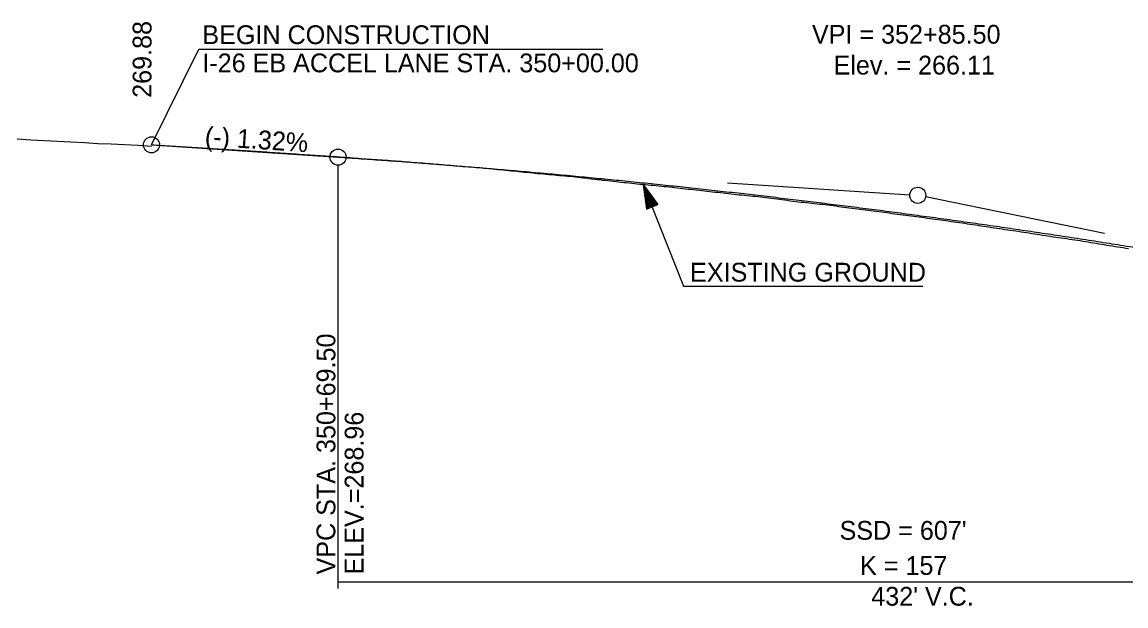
# Model space of a CAD drawing. Extents: x 69 to 2003113, y 512 to 837401.
# Drawn here: x 1913314.9 to 1913726.1, y 828640.4 to 828857.9 of the extents above; entities that cross this region are included whole.
import ezdxf

# ---------------------------------------------------------------- set-up
doc = ezdxf.new("R2010")
doc.units = 0
for name, color, linetype in [('BR_CENTER LINE BASELINE', 7, 'Continuous'), ('BR_CONCRETE', 7, 'Continuous'), ('BR_GRID DOTS', 7, 'Continuous'), ('BR_GRID LINES', 7, 'Continuous'), ('BR_TEXT', 7, 'Continuous'), ('RD_PD_ALT1_TrvlWay', 7, 'Continuous'), ('RD_SHT_IplotShp', 7, 'Continuous')]:
    doc.layers.add(name, color=color, linetype=linetype)

msp = doc.modelspace()

# ---------------------------------------------------------------- linework, layer by layer
at = {"layer": 'BR_CENTER LINE BASELINE'}
for p, q in [((1913577.73, 828798.04), (1913645.59, 828793.57)), ((1913718.15, 828779.19), (1913651.52, 828792.77))]:
    msp.add_line(p, q, dxfattribs=at)
for centre in [(1913363.08, 828812.18), (1913648.58, 828793.37)]:
    msp.add_circle(centre, 3, dxfattribs=at)
at = {"layer": 'BR_GRID DOTS'}
for p, q in [((1913432.58, 828646.85), (1913432.58, 828804.6)), ((1913432.58, 828649.35), (1913864.58, 828649.35))]:
    msp.add_line(p, q, dxfattribs=at)
msp.add_lwpolyline([(1913363.08, 828812.18), (1913380.68, 828847.78), (1913531.21, 828847.78)], dxfattribs=at)
msp.add_circle((1913432.58, 828807.6), 3, dxfattribs=at)
at = {"layer": 'BR_GRID LINES'}
msp.add_line((1913363.08, 828812.18), (1913432.58, 828807.6), dxfattribs=at)
msp.add_spline([(1913432.58, 828807.6), (1913441.22, 828807.02), (1913449.86, 828806.42), (1913458.5, 828805.79), (1913467.14, 828805.14), (1913475.78, 828804.46), (1913484.42, 828803.76), (1913493.06, 828803.03), (1913501.7, 828802.29), (1913510.34, 828801.51), (1913518.98, 828800.72), (1913527.62, 828799.9), (1913536.26, 828799.06), (1913544.9, 828798.19), (1913553.54, 828797.3), (1913562.18, 828796.38), (1913570.82, 828795.44), (1913579.46, 828794.48), (1913588.1, 828793.5), (1913596.74, 828792.49), (1913605.38, 828791.45), (1913614.02, 828790.39), (1913622.66, 828789.31), (1913631.3, 828788.21), (1913639.94, 828787.08), (1913648.58, 828785.92), (1913657.22, 828784.75), (1913665.86, 828783.55), (1913674.5, 828782.32), (1913683.14, 828781.07), (1913691.78, 828779.8), (1913700.42, 828778.51), (1913709.06, 828777.19), (1913717.7, 828775.84), (1913726.34, 828774.47), (1913734.98, 828773.08), (1913743.62, 828771.67), (1913752.26, 828770.23), (1913760.9, 828768.77), (1913769.54, 828767.28), (1913778.18, 828765.77), (1913786.82, 828764.24), (1913795.46, 828762.68), (1913804.1, 828761.1), (1913812.74, 828759.49), (1913821.38, 828757.86), (1913830.02, 828756.21), (1913838.66, 828754.53), (1913847.3, 828752.83), (1913855.94, 828751.1), (1913864.58, 828749.35)], degree=3, dxfattribs=at)
at = {"layer": 'BR_TEXT'}
for points in [[(1913313.08, 828814.45), (1913318.08, 828814.09), (1913323.08, 828813.8), (1913328.08, 828813.52), (1913333.08, 828813.25), (1913338.08, 828812.99), (1913343.08, 828812.71), (1913348.08, 828812.57), (1913353.08, 828812.3), (1913358.08, 828812.02), (1913363.08, 828811.72)], [(1913363.08, 828812.18), (1913364.08, 828812.12), (1913365.08, 828812.06), (1913366.08, 828812), (1913367.08, 828811.94), (1913368.08, 828811.89), (1913369.08, 828811.83), (1913370.08, 828811.77), (1913371.08, 828811.71), (1913372.08, 828811.65), (1913373.08, 828811.59), (1913374.08, 828811.54), (1913375.08, 828811.48), (1913376.08, 828811.42), (1913377.08, 828811.36), (1913378.08, 828811.3), (1913379.08, 828811.24), (1913380.08, 828811.17), (1913381.08, 828811.11), (1913382.08, 828811.05), (1913383.08, 828810.99), (1913384.08, 828810.93), (1913385.08, 828810.87), (1913386.08, 828810.8), (1913387.08, 828810.74), (1913388.08, 828810.68), (1913389.08, 828810.61), (1913390.08, 828810.54), (1913391.08, 828810.47), (1913392.08, 828810.4), (1913393.08, 828810.33), (1913394.08, 828810.27), (1913395.08, 828810.2), (1913396.08, 828810.13), (1913397.08, 828810.07), (1913398.08, 828810.01), (1913399.08, 828809.94), (1913400.08, 828809.88), (1913401.08, 828809.82), (1913402.08, 828809.76), (1913403.08, 828809.7), (1913404.08, 828809.63), (1913405.08, 828809.57), (1913406.08, 828809.51), (1913407.08, 828809.45), (1913408.08, 828809.38), (1913409.08, 828809.31), (1913410.08, 828809.24), (1913411.08, 828809.17), (1913412.08, 828809.1), (1913413.08, 828809.03), (1913414.08, 828808.96), (1913415.08, 828808.89), (1913416.08, 828808.83), (1913417.08, 828808.76), (1913418.08, 828808.69), (1913419.08, 828808.62), (1913420.08, 828808.56), (1913421.08, 828808.49), (1913422.08, 828808.43), (1913423.08, 828808.37), (1913424.08, 828808.31), (1913425.08, 828808.24), (1913426.08, 828808.18), (1913427.08, 828808.12), (1913428.08, 828808.06), (1913429.08, 828808), (1913430.08, 828807.93), (1913431.08, 828807.87), (1913432.08, 828807.79), (1913433.08, 828807.71), (1913434.08, 828807.63), (1913435.08, 828807.56), (1913436.08, 828807.48), (1913437.08, 828807.4), (1913438.08, 828807.32), (1913439.08, 828807.24), (1913440.08, 828807.17), (1913441.08, 828807.09), (1913442.08, 828807.02), (1913443.08, 828806.95), (1913444.08, 828806.89), (1913445.08, 828806.82), (1913446.08, 828806.75), (1913447.08, 828806.68), (1913448.08, 828806.62), (1913449.08, 828806.55), (1913450.08, 828806.48), (1913451.08, 828806.42), (1913452.08, 828806.35), (1913453.08, 828806.27), (1913454.08, 828806.2), (1913455.08, 828806.12), (1913456.08, 828806.04), (1913457.08, 828805.96), (1913458.08, 828805.88), (1913459.08, 828805.81), (1913460.08, 828805.73), (1913461.08, 828805.65), (1913462.08, 828805.57), (1913463.08, 828805.49)], [(1913463.08, 828805.49), (1913464.08, 828805.41), (1913465.08, 828805.34), (1913466.08, 828805.26), (1913467.08, 828805.17), (1913468.08, 828805.08), (1913469.08, 828804.99), (1913470.08, 828804.91), (1913471.08, 828804.82), (1913472.08, 828804.73), (1913473.08, 828804.64), (1913474.08, 828804.55), (1913475.08, 828804.47), (1913476.08, 828804.38), (1913477.08, 828804.3), (1913478.08, 828804.22), (1913479.08, 828804.14), (1913480.08, 828804.07), (1913481.08, 828803.99), (1913482.08, 828803.92), (1913483.08, 828803.84), (1913484.08, 828803.77), (1913485.08, 828803.69), (1913486.08, 828803.61), (1913487.08, 828803.52), (1913488.08, 828803.43), (1913489.08, 828803.33), (1913490.08, 828803.23), (1913491.08, 828803.13), (1913492.08, 828803.03), (1913493.08, 828802.94), (1913494.08, 828802.84), (1913495.08, 828802.74), (1913496.08, 828802.64), (1913497.08, 828802.54), (1913498.08, 828802.45), (1913499.08, 828802.35), (1913500.08, 828802.25), (1913501.08, 828802.15), (1913502.08, 828802.05), (1913503.08, 828801.95), (1913504.08, 828801.85), (1913505.08, 828801.75), (1913506.08, 828801.65), (1913507.08, 828801.55), (1913508.08, 828801.45), (1913509.08, 828801.35), (1913510.08, 828801.26), (1913511.08, 828801.16), (1913512.08, 828801.07), (1913513.08, 828800.97), (1913514.08, 828800.88), (1913515.08, 828800.8), (1913516.08, 828800.71), (1913517.08, 828800.62), (1913518.08, 828800.54), (1913519.08, 828800.45), (1913520.08, 828800.36), (1913521.08, 828800.27), (1913522.08, 828800.18), (1913523.08, 828800.06), (1913524.08, 828799.94), (1913525.08, 828799.82), (1913526.08, 828799.69), (1913527.08, 828799.57), (1913528.08, 828799.44), (1913529.08, 828799.32), (1913530.08, 828799.2), (1913531.08, 828799.07), (1913532.08, 828798.95), (1913533.08, 828798.83), (1913534.08, 828798.73), (1913535.08, 828798.62), (1913536.08, 828798.52), (1913537.08, 828798.41), (1913538.08, 828798.31), (1913539.08, 828798.2), (1913540.08, 828798.1), (1913541.08, 828797.99), (1913542.08, 828797.89), (1913543.08, 828797.78), (1913544.08, 828797.68), (1913545.08, 828797.57), (1913546.08, 828797.47), (1913547.08, 828797.37), (1913548.08, 828797.28), (1913549.08, 828797.18), (1913550.08, 828797.09), (1913551.08, 828797), (1913552.08, 828796.9), (1913553.08, 828796.81), (1913554.08, 828796.71), (1913555.08, 828796.62), (1913556.08, 828796.52), (1913557.08, 828796.41), (1913558.08, 828796.3), (1913559.08, 828796.18), (1913560.08, 828796.06), (1913561.08, 828795.95), (1913562.08, 828795.83), (1913563.08, 828795.72)], [(1913563.08, 828795.72), (1913564.08, 828795.6), (1913565.08, 828795.48), (1913566.08, 828795.37), (1913567.08, 828795.25), (1913568.08, 828795.13), (1913569.08, 828795.02), (1913570.08, 828794.91), (1913571.08, 828794.8), (1913572.08, 828794.69), (1913573.08, 828794.59), (1913574.08, 828794.48), (1913575.08, 828794.37), (1913576.08, 828794.26), (1913577.08, 828794.15), (1913578.08, 828794.04), (1913579.08, 828793.93), (1913580.08, 828793.82), (1913581.08, 828793.71), (1913582.08, 828793.6), (1913583.08, 828793.5), (1913584.08, 828793.4), (1913585.08, 828793.3), (1913586.08, 828793.2), (1913587.08, 828793.1), (1913588.08, 828793), (1913589.08, 828792.9), (1913590.08, 828792.8), (1913591.08, 828792.7), (1913592.08, 828792.59), (1913593.08, 828792.47), (1913594.08, 828792.33), (1913595.08, 828792.19), (1913596.08, 828792.05), (1913597.08, 828791.91), (1913598.08, 828791.78), (1913599.08, 828791.64), (1913600.08, 828791.5), (1913601.08, 828791.36), (1913602.08, 828791.22), (1913603.08, 828791.09), (1913604.08, 828790.97), (1913605.08, 828790.87), (1913606.08, 828790.76), (1913607.08, 828790.66), (1913608.08, 828790.55), (1913609.08, 828790.44), (1913610.08, 828790.34), (1913611.08, 828790.23), (1913612.08, 828790.13), (1913613.08, 828790.02), (1913614.08, 828789.92), (1913615.08, 828789.8), (1913616.08, 828789.66), (1913617.08, 828789.52), (1913618.08, 828789.39), (1913619.08, 828789.25), (1913620.08, 828789.12), (1913621.08, 828788.98), (1913622.08, 828788.84), (1913623.08, 828788.71), (1913624.08, 828788.57), (1913625.08, 828788.44), (1913626.08, 828788.32), (1913627.08, 828788.2), (1913628.08, 828788.07), (1913629.08, 828787.95), (1913630.08, 828787.82), (1913631.08, 828787.69), (1913632.08, 828787.56), (1913633.08, 828787.44), (1913634.08, 828787.31), (1913635.08, 828787.18), (1913636.08, 828787.06), (1913637.08, 828786.93), (1913638.08, 828786.79), (1913639.08, 828786.65), (1913640.08, 828786.52), (1913641.08, 828786.39), (1913642.08, 828786.25), (1913643.08, 828786.12), (1913644.08, 828785.99), (1913645.08, 828785.85), (1913646.08, 828785.72), (1913647.08, 828785.58), (1913648.08, 828785.45), (1913649.08, 828785.32), (1913650.08, 828785.19), (1913651.08, 828785.05), (1913652.08, 828784.91), (1913653.08, 828784.77), (1913654.08, 828784.63), (1913655.08, 828784.5), (1913656.08, 828784.36), (1913657.08, 828784.22), (1913658.08, 828784.08), (1913659.08, 828783.94), (1913660.08, 828783.8), (1913661.08, 828783.66), (1913662.08, 828783.52), (1913663.08, 828783.37)], [(1913663.08, 828783.37), (1913664.08, 828783.23), (1913665.08, 828783.08), (1913666.08, 828782.93), (1913667.08, 828782.78), (1913668.08, 828782.63), (1913669.08, 828782.48), (1913670.08, 828782.34), (1913671.08, 828782.19), (1913672.08, 828782.04), (1913673.08, 828781.89), (1913674.08, 828781.74), (1913675.08, 828781.58), (1913676.08, 828781.43), (1913677.08, 828781.28), (1913678.08, 828781.13), (1913679.08, 828780.98), (1913680.08, 828780.83), (1913681.08, 828780.68), (1913682.08, 828780.53), (1913683.08, 828780.38), (1913684.08, 828780.23), (1913685.08, 828780.08), (1913686.08, 828779.95), (1913687.08, 828779.79), (1913688.08, 828779.64), (1913689.08, 828779.49), (1913690.08, 828779.34), (1913691.08, 828779.19), (1913692.08, 828779.03), (1913693.08, 828778.88), (1913694.08, 828778.73), (1913695.08, 828778.58), (1913696.08, 828778.43), (1913697.08, 828778.27), (1913698.08, 828778.11), (1913699.08, 828777.96), (1913700.08, 828777.81), (1913701.08, 828777.66), (1913702.08, 828777.52), (1913703.08, 828777.37), (1913704.08, 828777.22), (1913705.08, 828777.07), (1913706.08, 828776.92), (1913707.08, 828776.78), (1913708.08, 828776.63), (1913709.08, 828776.48), (1913710.08, 828776.33), (1913711.08, 828776.17), (1913712.08, 828776), (1913713.08, 828775.84), (1913714.08, 828775.67), (1913715.08, 828775.51), (1913716.08, 828775.34), (1913717.08, 828775.18), (1913718.08, 828775.01), (1913719.08, 828774.85), (1913720.08, 828774.69), (1913721.08, 828774.52), (1913722.08, 828774.35), (1913723.08, 828774.19), (1913724.08, 828774.03), (1913725.08, 828773.87), (1913726.08, 828773.71), (1913727.08, 828773.55)]]:
    msp.add_lwpolyline(points, dxfattribs=at)
at = {"layer": 'RD_PD_ALT1_TrvlWay'}
for p, q in [((1913546.32, 828797.45), (1913561.28, 828759.49)), ((1913549.62, 828789.08), (1913546.32, 828797.45)), ((1913546.32, 828797.45), (1913551.71, 828789.9)), ((1913546.32, 828797.45), (1913547.53, 828788.25)), ((1913547.53, 828788.25), (1913551.71, 828789.9)), ((1913561.28, 828759.49), (1913650.47, 828759.49))]:
    msp.add_line(p, q, dxfattribs=at)
for points in [[(1913549.52, 828789.16), (1913546.45, 828796.95), (1913549.49, 828789.08), (1913546.52, 828796.56), (1913549.39, 828789.08), (1913546.55, 828796.29), (1913549.28, 828789.06), (1913546.58, 828795.96), (1913549.2, 828789.01), (1913546.65, 828795.47), (1913549.08, 828788.94), (1913546.74, 828794.94), (1913548.97, 828788.94), (1913546.79, 828794.55), (1913548.89, 828788.89), (1913546.85, 828794.09), (1913548.78, 828788.9), (1913546.91, 828793.69), (1913548.72, 828788.8), (1913546.95, 828793.35), (1913548.58, 828788.79), (1913547, 828792.85), (1913548.49, 828788.73), (1913547.12, 828792.25), (1913548.39, 828788.67), (1913547.12, 828791.83), (1913548.29, 828788.63), (1913547.21, 828791.21), (1913548.17, 828788.62), (1913547.31, 828790.71), (1913548.07, 828788.52), (1913547.36, 828790.27), (1913547.97, 828788.52), (1913547.4, 828789.86), (1913547.88, 828788.43), (1913547.47, 828789.37), (1913547.77, 828788.47), (1913547.55, 828788.82), (1913547.65, 828788.46)], [(1913546.6, 828796.93), (1913549.64, 828789.2), (1913546.76, 828796.67), (1913549.75, 828789.24), (1913546.91, 828796.43), (1913549.83, 828789.24), (1913547.09, 828796.22), (1913549.89, 828789.28), (1913547.3, 828795.96), (1913549.98, 828789.3), (1913547.47, 828795.71), (1913550.05, 828789.33), (1913547.69, 828795.42), (1913550.15, 828789.34), (1913547.93, 828795.06), (1913550.26, 828789.41), (1913548.14, 828794.74), (1913550.34, 828789.4), (1913548.37, 828794.41), (1913550.42, 828789.45), (1913548.61, 828794.1), (1913550.51, 828789.49), (1913548.85, 828793.75), (1913550.56, 828789.57), (1913549.17, 828793.3), (1913550.66, 828789.56), (1913549.4, 828793.01), (1913550.74, 828789.56), (1913549.69, 828792.63), (1913550.82, 828789.63), (1913549.93, 828792.22), (1913550.91, 828789.68), (1913550.16, 828791.91), (1913551, 828789.78), (1913550.41, 828791.63), (1913551.07, 828789.8), (1913550.69, 828791.16), (1913551.21, 828789.78), (1913550.88, 828790.89), (1913551.35, 828789.84), (1913551.06, 828790.72), (1913551.46, 828789.98), (1913551.58, 828789.93), (1913551.42, 828789.97)]]:
    msp.add_lwpolyline(points, dxfattribs=at)

# ---------------------------------------------------------------- texts
at = {"layer": 'BR_CENTER LINE BASELINE'}
msp.add_text('(-) 1.32%', height=7, rotation=356.23, dxfattribs=at).set_placement((1913382.8, 828811.93))
at = {"layer": 'BR_CONCRETE'}
for s, p in [('VPC STA. 350+69.50 ', (1913431.58, 828652.11)), ('ELEV.=268.96', (1913442.08, 828652.11))]:
    msp.add_text(s, height=7, rotation=90, dxfattribs=at).set_placement(p)
at = {"layer": 'BR_GRID DOTS'}
for s, p in [("SSD = 607'", (1913619.45, 828665.05)), ('K = 157', (1913627.09, 828651.95)), ("432' V.C.", (1913631.26, 828640.5))]:
    msp.add_text(s, height=7, dxfattribs=at).set_placement(p)
at = {"layer": 'RD_PD_ALT1_TrvlWay'}
msp.add_text('EXISTING GROUND', height=7, dxfattribs=at).set_placement((1913563.75, 828761.22))
at = {"layer": 'RD_SHT_IplotShp'}
msp.add_text('269.88', height=7, rotation=90, dxfattribs=at).set_placement((1913363.08, 828829.68))
for s, p in [('BEGIN CONSTRUCTION ', (1913382.04, 828849.7)), ('VPI = 352+85.50', (1913609.16, 828849.87)), ('I-26 EB ACCEL LANE STA. 350+00.00', (1913382.04, 828839.2)), ('Elev. = 266.11', (1913617.22, 828838.37))]:
    msp.add_text(s, height=7, dxfattribs=at).set_placement(p)

doc.saveas('drawing.dxf')
